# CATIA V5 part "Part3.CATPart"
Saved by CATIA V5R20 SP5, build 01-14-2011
Part number: 卡瓦
Bounding box of the stored display mesh (mm): x -44 to 74, y -43.997 to 16, z 0 to 50
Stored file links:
  E:\scc\Part3.CATPart
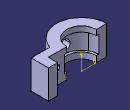
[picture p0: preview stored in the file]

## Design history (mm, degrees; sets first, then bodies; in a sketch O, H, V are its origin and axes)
Body1 (main body)
  Sketch1 on xy-plane, origin (0, 0, 0), H (1, 0, 0), V (0, 1, 0)
    arc A1 centre (0, 0) radius 26 from (-26, 0) to (26, 0) ccw
    arc A2 centre (0, 0) radius 44 from (-44, 0) to (41.7133, -14) ccw
    line L1 (-44, 0) -> (-26, 0)
    point P1 (-44, 0)
    point P2 (58, 0)
    line L2 (58, 0) -> (58, 16)
    line L3 (58, 16) -> (74, 16)
    line L4 (74, 16) -> (74, -14)
    line L5 (74, -14) -> (41.7133, -14)
    line L6 (26, 0) -> (58, 0)
    length L2 = 16
    length L3 = 16
    length L4 = 30
    distance O L4 = 74
    radius A1 = 26
    radius A2 = 44
    coincidence: P1 H, P2 L1
    horizontal: L1 H, L3 H, L5 H, L6 H
    vertical: L2 V, L4 V
  Pad1: profile Sketch1, direction (0, 0, 1), length 50
  Sketch2 on zx-plane, origin (0, 0, 0), H (-1, 0, 0), V (0, 0, 1)
    point P1 (17.5662, 25.4942)
    line L1 (30, 40.4942) -> (30, 10.4942)
    line L2 (30, 10.4942) -> (5.1324, 10.4942)
    line L3 (5.1324, 10.4942) -> (5.1324, 40.4942)
    line L4 (5.1324, 40.4942) -> (30, 40.4942)
    reference projected line E1 through (0, 0) direction (0, 1) from axis of face of Pad1 from Sketch1.A1
    distance L1 E1 = 30
    length L1 = 30
    vertical: L1 V, L3 V
    horizontal: L2 H, L4 H
    equidistance: L1 L3 P1, L2 L4 P1
  Sketch3 on face of Pad1 from Sketch1.L1, origin (0, 0, 0), H (-1, 0, 0), V (0, 0, 1)
  Groove1: profile Sketch2, axis axis of face of Pad1 from Sketch1.A1, angle 360
  Sketch4 on face of Pad1 from Sketch1.L1, origin (0, 0, 0), H (-1, 0, 0), V (0, 0, 1)
    circle A1 centre (0, 24.0102) radius 9.0126
    point P1 (0, 24.0102)
    coincidence: P1 V
  Pocket1: profile Sketch4, direction (0, -1, 0), length 100
  Sketch5 on face of Pad1 from Sketch1.L6, origin (0, 0, 0), H (-1, 0, 0), V (0, 0, 1)
    circle A1 centre (-44.3275, 26.2988) radius 5.7625
  Pocket2: profile Sketch5, direction (0, -1, 0), length 10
